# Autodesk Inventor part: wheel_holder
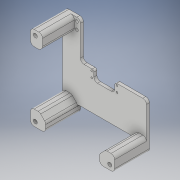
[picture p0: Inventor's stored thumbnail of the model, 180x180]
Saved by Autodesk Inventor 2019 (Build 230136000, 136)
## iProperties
Created: 2018-06
Part Number: wheel_holder
Material: Generic
Document SubType Name: Modeling
Designer: felldings
Density: 1 g/cm^3
Appearance: Default
Author: felldings
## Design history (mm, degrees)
sketch "Sketch8"
  geometry: L1 (0, 0)-(140, 0); L2 (140, 0)-(140, 78); L3 (140, 78)-(87.5, 78); L4 (87.5, 78)-(87.5, 62); L5 (87.5, 62)-(52.5, 62); L6 (52.5, 62)-(52.5, 78); L7 (52.5, 78)-(30, 78); L8 (30, 78)-(30, 140); L9 (30, 140)-(0, 140); L10 (0, 140)-(0, 0); 1 further point
  constraints: 20 end point, 8 perpendicular, 2 point on line, 1 horizontal
  dimensions: "d55" = 70 distance from line of L10 point (70, 70); "d56" = 70 distance from line of L1 point (70, 70); "d57" = 8 distance from line of L5 point (70, 70); "d58" = 16 distance of L5.end L6.end; "d59" = 35 distance of L4.end L5.end; "d60" = 17.5 distance from line of point (70, 70) L6; "d61" = 40 distance from line of point (70, 70) L8; "d62" = 140 distance between parallel lines of L1 L9; "d63" = 140 distance of L1.start L1.end
extrude "base_plate" new body sketch "Sketch8" distance "d64" = 5; taper "d65" = 0 deg
sketch "Sketch9"
  geometry: L1 (52.5, 62)-(52.5, 78) reference; L2 (0, 0)-(140, 0) reference; 4 further points
  dimensions: "d66" = 42 distance of point (91, 65) point (49, 65); "d67" = 42 distance of point (91, 75) point (49, 75); "d68" = 10 distance of point (49, 65) point (49, 75); "d69" = 10 distance of point (91, 65) point (91, 75); "d70" = 3.5 distance from line of L1 point (49, 75); "d71" = 3.5 distance from line of L1 point (49, 65); "d72" = 65 distance from line of L2 point (91, 65); "d73" = 65 distance from line of L2 point (49, 65)
hole "pcb_mount_holes" sketch "Sketch9" at (49, 75), (49, 65), (91, 75), (91, 65) diameter "d74" = 3; stored, may be unused: countersink angle "d78" = 90 deg, drill point angle "d80" = 118 deg; dims "d75" = 6, "d76" = 4, "d77" = 2, "d79" = 8
sketch "Sketch10"
  geometry: L1 (0, 0)-(25, 0); L2 (25, 0)-(25, 25); L3 (25, 25)-(0, 25); L4 (0, 25)-(0, 0); L5 (0, 0)-(140, 0) reference; L6 (140, 0)-(115, 0); L7 (115, 0)-(115, 25); L8 (115, 25)-(140, 25); L9 (140, 25)-(140, 0); L10 (0, 140)-(0, 0) reference; L11 (0, 140)-(20, 140); L12 (20, 140)-(20, 115); L13 (20, 115)-(0, 115); L14 (0, 115)-(0, 140); C1 r 65 at (70, 70)
  constraints: 24 end point, 6 parallel, 3 horizontal, 3 perpendicular, 1 centre point
  dimensions: "d81" = 130 diameter of C1; "d82" = 20 distance of L12.end L13.end; "d83" = 25 distance of L11.end L12.end; "d84" = 25 distance of L2.end L3.end; "d85" = 25 distance of L1.end L2.end; "d86" = 25 distance of L6.end L7.end; "d87" = 25 distance of L7.end L8.end
extrude "distance_blocks" join sketch "Sketch10" distance "d88" = 53; taper "d89" = 0 deg
chamfer "space_for_digitwheel" distance "d90" = 10; stored, may be unused: second distance "d91" = 2, angle "d92" = 45 deg
chamfer "space_for_digitwheel2" distance "d93" = 5; stored, may be unused: second distance "d94" = 2, angle "d95" = 45 deg
sketch "Sketch11"
  geometry: L1 (30, 78)-(30, 140) reference; L2 (30, 140)-(20, 140) reference; 3 further points
  dimensions: "d96" = 6 distance from line of L1 point (24, 134); "d97" = 6 distance from line of L1 point (24, 122); "d98" = 6 distance from line of L2 point (24, 134); "d99" = 12 distance of point (24, 134) point (24, 122)
hole "cable_fixation_holes" sketch "Sketch11" at (24, 134), (24, 122) diameter "d100" = 5; stored, may be unused: countersink angle "d104" = 90 deg, drill point angle "d106" = 118 deg; dims "d101" = 6, "d102" = 4, "d103" = 2, "d105" = 8
sketch "Sketch12"
  geometry: L1 (0, 0)-(140, 0) reference; L2 (125, 25)-(115, 15) reference; L3 (25, 0)-(115, 0); L4 (115, 0)-(115, 15); L5 (115, 15)-(25, 15); L6 (25, 15)-(25, 0); L7 (25, 15)-(25, 0) reference
  constraints: 8 end point, 2 parallel, 1 collinear, 1 horizontal, 1 perpendicular, 1 point on line
extrude "lighting space" cut sketch "Sketch12" distance "d107" = 53; taper "d108" = 0 deg
sketch "Sketch13"
  geometry: L1 (0, 140)-(0, 0) reference; L2 (0, 0)-(-25, 0) reference; L3 (-115, 0)-(-140, 0) reference; L4 (-140, 0)-(-140, 78) reference; L5 (-30, 140)-(0, 140) reference; 3 further points
  dimensions: "d109" = 8 distance from line of L1 point (-8, 8); "d110" = 8 distance from line of L2 point (-8, 8); "d111" = 8 distance from line of L3 point (-132, 8); "d112" = 8 distance from line of L4 point (-132, 8); "d113" = 8 distance from line of L5 point (-8, 132); "d114" = 8 distance from line of L1 point (-8, 132)
hole "grouping_holes" sketch "Sketch13" at (-8, 8), (-8, 132), (-132, 8) diameter "d115" = 6.5; stored, may be unused: countersink angle "d119" = 90 deg, drill point angle "d121" = 118 deg; dims "d116" = 6, "d117" = 4, "d118" = 2, "d120" = 8
fillet "Fillet4" dims "d122" = 3
fillet "Fillet5" dims "d123" = 6
fillet "Fillet6" dims "d124" = 6
fillet "Fillet7" dims "d125" = 3
sketch "Sketch14"
  geometry: L1 (0, 128)-(0, 0) reference; L2 (0, -6)-(58, -6) reference; 2 further points
  dimensions: "d126" = 29 distance from line of L1 point (29, 118); "d127" = 29 distance from line of L1 point (29, 10); "d128" = 108 distance of point (29, 10) point (29, 118); "d129" = 16 distance from line of L2 point (29, 10)
hole "footholes" sketch "Sketch14" at (29, 118), (29, 10) diameter "d130" = 4.5; stored, may be unused: countersink angle "d134" = 90 deg, drill point angle "d136" = 118 deg; dims "d131" = 6, "d132" = 4, "d133" = 2, "d135" = 8
body "Solid3"
